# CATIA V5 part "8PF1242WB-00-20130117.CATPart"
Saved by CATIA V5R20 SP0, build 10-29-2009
Part number: 8PF1242WB-00-20130117
Revision: ANY
Definition: UNKNOWN
Nomenclature: 8PF1242WB-00-20130117
Source: Unknown
Bounding box of the stored display mesh (mm): x 1756.092 to 1956.092, y 1456.713 to 1463.638, z 0 to 12
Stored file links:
  C:\Users\Utente\Desktop\IO LAVORO\3D X SITO CF\CUMSA\3D files PF\PF 124200\8PF1242WB-00-20130117.CATPart
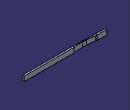
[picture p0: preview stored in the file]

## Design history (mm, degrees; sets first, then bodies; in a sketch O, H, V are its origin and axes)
Body1 "Cortar-Extruir1" (main body)
  Solid1: solid without history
